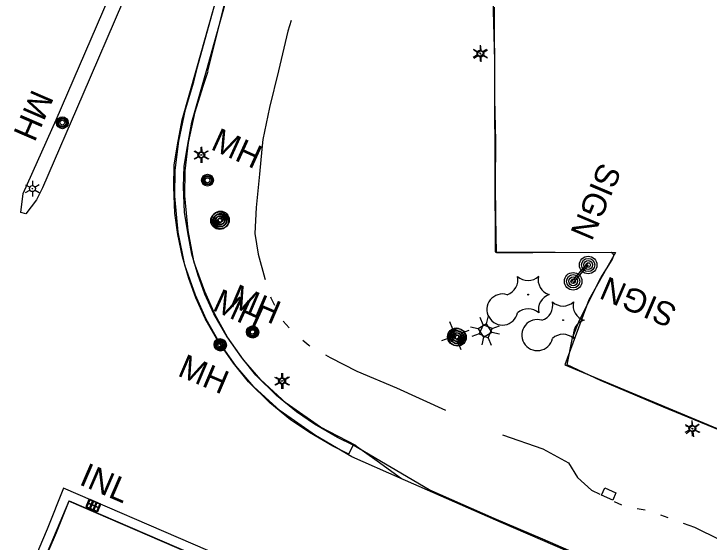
# Model space of a CAD drawing. Extents: x 588843 to 2552415, y 180129 to 269402.
# Drawn here: x 593439.7 to 593615.7, y 185762.9 to 185896.7 of the extents above; entities that cross this region are included whole.
import ezdxf

# ---------------------------------------------------------------- set-up
doc = ezdxf.new("R2010")
doc.units = 0
for name, color, linetype in [('Default', 7, 'Continuous'), ('E_AREA', 7, 'Continuous'), ('E_DRN', 7, 'Continuous'), ('E_DRN_Text', 7, 'Continuous'), ('E_DWY', 7, 'Continuous'), ('E_LAND_Vegetation', 7, 'Continuous'), ('E_LTG', 7, 'Continuous'), ('E_MISCPROP', 7, 'Continuous'), ('E_RDWY', 7, 'Continuous'), ('E_RDWY_C_and_G', 7, 'Continuous'), ('E_RDWY_Gravel', 7, 'Continuous'), ('E_SGN', 7, 'Continuous'), ('E_SGN_Text', 7, 'Continuous'), ('E_UTL_AG_Bold', 7, 'Continuous'), ('E_UTL_MH', 7, 'Continuous'), ('E_UTL_MH_Text', 7, 'Continuous'), ('E_WTR_P', 7, 'Continuous')]:
    doc.layers.add(name, color=color, linetype=linetype)

# ---------------------------------------------------------------- blocks, each defined once
blk = doc.blocks.new('LPOL')
at = {"layer": 'Default'}
for p, q in [((-4, 0), (-1.5, 0)), ((-0.75, 1.3), (-2, 3.46)), ((0.75, 1.3), (2, 3.46)), ((1.5, 0), (4, 0)), ((-2, -3.46), (-0.75, -1.3)), ((2, -3.46), (0.75, -1.3))]:
    blk.add_line(p, q, dxfattribs=at)
for radius in [1.5, 1.5, 1.5, 0.125]:
    blk.add_circle((0, 0), radius, dxfattribs=at)
blk = doc.blocks.new('POLE')
at = {"layer": 'Default'}
for radius in [4.46, 3.35, 2.23, 1.12]:
    blk.add_circle((0, 0), radius, dxfattribs=at)
blk = doc.blocks.new('MHO')
at = {"layer": 'Default'}
for centre, radius in [((0.08, -0.12), 3), ((0.08, -0.12), 2.43), ((0.07, -0.15), 1.94), ((0.02, -0.16), 1.21)]:
    blk.add_circle(centre, radius, dxfattribs=at)
blk = doc.blocks.new('MHT')
at = {"layer": 'E_UTL_MH_Text'}
blk.add_text('MH', height=12, dxfattribs=at).set_placement((-9.81, -6))
blk = doc.blocks.new('PED')
at = {"layer": 'Default'}
for p, q in [((-2.5, 2.5), (-5.33, 5.33)), ((2.5, 2.5), (5.33, 5.33)), ((-2.5, -2.5), (-5.33, -5.33)), ((2.5, -2.5), (5.33, -5.33))]:
    blk.add_line(p, q, dxfattribs=at)
blk.add_lwpolyline([(-2.5, -2.5), (2.5, -2.5), (2.5, 2.5), (-2.5, 2.5)], close=True, dxfattribs=at)
blk = doc.blocks.new('SIGN')
at = {"layer": 'Default'}
blk.add_text('SIGN', height=12, dxfattribs=at).set_placement((-18.55, -6))
blk = doc.blocks.new('CTRE')
at = {"layer": 'Default'}
blk.add_circle((0, 0), 0.223, dxfattribs=at)
for centre, start, end in [((-11.97, 8.96), 280.2067, 5.9716), ((1.81, 14.92), 220.2113, 305.9762), ((13.83, 5.89), 160.2113, 245.9762), ((-13.83, -5.9), 340.2113, 65.9762), ((12.03, -9.04), 185.9272, 100.2511), ((-1.81, -14.93), 40.2113, 125.9762)]:
    blk.add_arc(centre, 7.87, start, end, dxfattribs=at)
blk = doc.blocks.new('INLO')
at = {"layer": 'E_DRN'}
for p, q in [((2, -4), (2, 0)), ((4, -4), (4, 0)), ((6, -2), (0, -2))]:
    blk.add_line(p, q, dxfattribs=at)
blk.add_lwpolyline([(0, -4), (6, -4), (6, 0), (0, 0), (0, -4)], close=True, dxfattribs=at)
blk = doc.blocks.new('INLT_25')
at = {"layer": 'E_DRN_Text'}
blk.add_text('INL', height=12, dxfattribs=at).set_placement((-11.03, -6))
blk = doc.blocks.new('INLO_3')
at = {"layer": 'E_DRN'}
for p, q in [((6.6, -13.1), (6.6, 0)), ((13.1, -13.1), (13.1, 0)), ((19.7, -6.6), (0, -6.6))]:
    blk.add_line(p, q, dxfattribs=at)
blk.add_lwpolyline([(0, -13.1), (19.7, -13.1), (19.7, 0), (0, 0)], close=True, dxfattribs=at)
blk = doc.blocks.new('INLT_39_1')
at = {"layer": 'E_DRN_Text'}
blk.add_text('INL', height=39.37, dxfattribs=at).set_placement((-36.2, -19.7))
blk = doc.blocks.new('MHO_3')
at = {"layer": 'E_UTL_MH'}
for centre, radius in [((0.3, -0.4), 9.84), ((0.3, -0.4), 7.98), ((0.2, -0.5), 6.35), ((0.1, -0.5), 3.97)]:
    blk.add_circle(centre, radius, dxfattribs=at)
blk = doc.blocks.new('MHT_3')
at = {"layer": 'E_UTL_MH_Text'}
blk.add_text('MH', height=39.37, dxfattribs=at).set_placement((-32.2, -19.7))
blk = doc.blocks.new('PED_3')
at = {"layer": 'E_UTL_AG_Bold'}
for p, q in [((-8.2, 8.2), (-17.5, 17.5)), ((8.2, 8.2), (17.5, 17.5)), ((-8.2, -8.2), (-17.5, -17.5)), ((8.2, -8.2), (17.5, -17.5))]:
    blk.add_line(p, q, dxfattribs=at)
blk.add_lwpolyline([(-8.2, -8.2), (8.2, -8.2), (8.2, 8.2), (-8.2, 8.2)], close=True, dxfattribs=at)
blk = doc.blocks.new('LPOL_4')
at = {"layer": 'E_LTG'}
for p, q in [((-13.1, 0), (-4.9, 0)), ((-2.5, 4.3), (-6.6, 11.4)), ((2.5, 4.3), (6.6, 11.4)), ((4.9, 0), (13.1, 0)), ((-6.6, -11.4), (-2.5, -4.3)), ((6.6, -11.4), (2.5, -4.3))]:
    blk.add_line(p, q, dxfattribs=at)
for radius in [4.92, 4.92, 4.92, 0.41]:
    blk.add_circle((0, 0), radius, dxfattribs=at)
blk = doc.blocks.new('POLE_3')
at = {"layer": 'E_MISCPROP'}
for radius in [14.6, 11, 7.32, 3.66]:
    blk.add_circle((0, 0), radius, dxfattribs=at)
blk = doc.blocks.new('SIGN_3')
at = {"layer": 'E_SGN'}
blk.add_text('SIGN', height=39.37, dxfattribs=at).set_placement((-56.1, -19.7))

msp = doc.modelspace()

# ---------------------------------------------------------------- linework, layer by layer
at = {"layer": 'E_AREA'}
msp.add_lwpolyline([(593591.34, 185773.52), (593588.51, 185774.78), (593589.34, 185776.65), (593592.17, 185775.39), (593591.34, 185773.52)], close=True, dxfattribs=at)
at = {"layer": 'E_DWY'}
for points in [[(593561.3, 185898.37), (593561.59, 185836.43), (593592.09, 185836.3), (593585.32, 185824.31), (593579.2, 185807.78), (593629.08, 185786.97), (593683.34, 185763.77), (593715.78, 185763.83), (593758.03, 185763.57), (593758.13, 185803.19), (593757.72, 185847.98), (593757.71, 185903.71), (593757.53, 185954.3)], [(593626.39, 185787.96), (593604.22, 185797.06), (593588.26, 185803.86), (593579.8, 185807.78), (593581.19, 185814.63), (593582.97, 185819.1), (593588.33, 185829.86), (593591.19, 185834.44), (593591.67, 185835.51), (593591.5, 185835.94), (593590.92, 185836.23), (593571.13, 185836.15), (593561.94, 185836.17), (593561.79, 185845.33), (593561.7, 185853.71), (593561.78, 185864.51), (593561.53, 185875.2), (593561.46, 185884.92), (593561.05, 185900.77)]]:
    msp.add_lwpolyline(points, dxfattribs=at)
at = {"layer": 'E_RDWY'}
for points in [[(593486.2, 185883.3), (593489.18, 185893.96), (593493.89, 185911.07), (593499.24, 185928.93), (593507.1, 185955.12), (593509.61, 185962.65), (593517.48, 185983.79), (593527.72, 186012.54), (593531.1, 186022.16), (593535.59, 186036.96), (593539.47, 186051.68), (593541.2, 186062.67), (593545.15, 186089.33), (593548.03, 186107.77), (593551.11, 186127.76), (593554.74, 186154.6), (593556.82, 186170.65)], [(593491.32, 185955.6), (593483.2, 185936.21), (593475.03, 185917.29), (593467.27, 185899.56), (593457.19, 185876.3), (593446.96, 185852.66), (593445.45, 185849.57), (593442.79, 185846.03), (593441.53, 185846.44), (593442.11, 185851.19), (593450.4, 185869.87), (593465.24, 185904.11), (593481.63, 185942.45), (593487.18, 185955.06)], [(593486.07, 185882.94), (593490.12, 185897.35), (593494.11, 185911.31), (593497.9, 185924.36), (593502.15, 185939.12), (593506.3, 185953.15)], [(593759.1, 185683.31), (593742.04, 185690.53), (593728.3, 185696.69), (593709.33, 185704.73), (593695.77, 185710.83), (593682.84, 185716.47), (593670.2, 185721.87), (593658.17, 185727.03), (593647.4, 185731.86), (593631.92, 185738.54), (593621.67, 185743), (593610.57, 185747.71), (593598.94, 185752.59), (593585.45, 185758.54), (593573.64, 185763.64), (593561.33, 185768.89), (593544.91, 185776.17), (593525.62, 185787.49)], [(593759.23, 185683.39), (593739.55, 185691.58), (593712.69, 185703.4), (593684.94, 185715.45), (593651.85, 185729.61), (593625.47, 185740.91), (593596.7, 185753.38), (593563.11, 185767.85), (593537.55, 185779.12), (593525.28, 185784.5)]]:
    msp.add_lwpolyline(points, dxfattribs=at)
msp.add_lwpolyline([(593453.69, 185773.4), (593523.56, 185743.19), (593588.11, 185715.4), (593631.1, 185696.92), (593667.51, 185681.1), (593666.73, 185678.74), (593618.51, 185694.03), (593571.62, 185708.83), (593555.14, 185714.19), (593536.4, 185722.25), (593496.73, 185739.41), (593448.26, 185760.34), (593453.69, 185773.4)], close=True, dxfattribs=at)
at = {"layer": 'E_RDWY_C_and_G'}
msp.add_line((593524.54, 185785.23), (593525.62, 185787.49), dxfattribs=at)
for points in [[(593525.28, 185784.5), (593516.08, 185789.89), (593507.12, 185796.18), (593500.49, 185802.26), (593495.89, 185807.55), (593491.73, 185813.52), (593488.45, 185819.36), (593485.74, 185825.44), (593482.99, 185833.08), (593481.36, 185841.45), (593480.5, 185850.56), (593480.6, 185857.14), (593481.52, 185864.5), (593483.18, 185872.5), (593485.32, 185879.46), (593486.2, 185883.3)], [(593524.54, 185785.23), (593520.46, 185787.18), (593514.54, 185790.64), (593509.77, 185793.89), (593504.56, 185798.16), (593499.13, 185803.52), (593495.33, 185808.28), (593491.66, 185813.55), (593488.12, 185819.59), (593485.79, 185824.76), (593484.01, 185829.67), (593482.39, 185835.21), (593481.28, 185840.87), (593480.44, 185846.23), (593480.21, 185852.92), (593480.35, 185858.38), (593481.19, 185863.53), (593482.38, 185869.88), (593486.07, 185882.94)], [(593525.62, 185787.49), (593521.63, 185789.39), (593515.87, 185792.75), (593511.27, 185795.89), (593506.24, 185800.02), (593501, 185805.19), (593497.34, 185809.78), (593493.77, 185814.9), (593490.34, 185820.74), (593488.11, 185825.7), (593486.38, 185830.45), (593484.82, 185835.81), (593483.74, 185841.3), (593482.93, 185846.46), (593482.71, 185852.93), (593482.84, 185858.15), (593483.65, 185863.1), (593484.82, 185869.31), (593488.48, 185882.26)], [(593526.49, 185787.32), (593517.38, 185792.03), (593508.69, 185798.13), (593502.28, 185804.01), (593497.86, 185809.09), (593493.85, 185814.85), (593490.68, 185820.48), (593488.06, 185826.38), (593485.4, 185833.75), (593483.84, 185841.81), (593483, 185850.66), (593483.1, 185856.96), (593483.98, 185864.09), (593485.61, 185871.88), (593487.7, 185878.69), (593488.91, 185882.24)]]:
    msp.add_lwpolyline(points, dxfattribs=at)
for points in [[(593448.13, 185766.21), (593446.03, 185761.25), (593445.89, 185760.73), (593445.4, 185758.88), (593471.82, 185747.59), (593502.39, 185734.18), (593537.96, 185718.62), (593551.21, 185713.11), (593555.3, 185711.56), (593576.13, 185704.66), (593609.59, 185694.25), (593642.06, 185683.63), (593668.03, 185675.84), (593670.7, 185682.2), (593650.33, 185690.99), (593611.9, 185707.52), (593580.22, 185721.35), (593554.46, 185732.38), (593530.38, 185742.76), (593496.85, 185757.3), (593485.12, 185762.4), (593452.33, 185776.58)], [(593484.13, 185760.1), (593453.68, 185773.27), (593450.44, 185765.26), (593448.36, 185760.33), (593472.81, 185749.89), (593503.4, 185736.47), (593538.94, 185720.91), (593552.13, 185715.43), (593556.13, 185713.91), (593576.9, 185707.03), (593610.35, 185696.63), (593642.8, 185686.01), (593666.59, 185678.87), (593667.44, 185680.89), (593649.35, 185688.7), (593610.91, 185705.23), (593579.23, 185719.06), (593553.48, 185730.09), (593529.39, 185740.47), (593495.86, 185755.01)]]:
    msp.add_lwpolyline(points, close=True, dxfattribs=at)
at = {"layer": 'E_RDWY_Gravel'}
for points in [[(593488.82, 185882.27), (593492.95, 185898.78), (593497.36, 185916.15), (593501.01, 185930), (593507.22, 185955.48)], [(593488.48, 185882.26), (593493.13, 185898.88), (593496.57, 185912.37), (593500.46, 185927.75), (593501.95, 185933.67), (593505.72, 185948.6), (593506.3, 185953.15)], [(593526.45, 185787.23), (593531.75, 185783.51), (593537.84, 185778.99)]]:
    msp.add_lwpolyline(points, dxfattribs=at)
at = {"layer": 'E_SGN'}
msp.add_line((593585.15, 185833.11), (593581.14, 185828.46), dxfattribs=at)
msp.add_lwpolyline([(593581.02, 185828.92), (593585.01, 185833.56)], dxfattribs=at)
at = {"layer": 'E_WTR_P'}
for points in [[(593509.9, 185895.03), (593509.12, 185892.32), (593506.77, 185882.26), (593504.49, 185872.96), (593502.78, 185864.91), (593502.54, 185862.44)], [(593502.54, 185862.44), (593501.94, 185856.15), (593501.07, 185847.66), (593500.71, 185841.06), (593501.59, 185835.88), (593503.3, 185829.7), (593503.38, 185829.42)], [(593504.73, 185825.02), (593504.81, 185824.75), (593505.73, 185822.94)], [(593507.93, 185818.91), (593509.45, 185817.18)], [(593512.86, 185814.1), (593514.39, 185812.81), (593514.66, 185812.66)], [(593518.65, 185810.35), (593519.82, 185809.68), (593526.52, 185806.22), (593536.64, 185802.01), (593548.99, 185796.32)], [(593563.43, 185790.11), (593573.68, 185786.52), (593580.16, 185782.97), (593582.45, 185779.28), (593585.96, 185776.09), (593588.05, 185775.07)], [(593591.71, 185773.24), (593593.54, 185772.32)], [(593597.52, 185771.47), (593599.54, 185771.11)], [(593603.41, 185769.81), (593605.34, 185769.12)], [(593609.19, 185767.74), (593612.06, 185766.71), (593631.41, 185757.17), (593635.93, 185754.95)]]:
    msp.add_lwpolyline(points, dxfattribs=at)

# ---------------------------------------------------------------- block references
at = {"layer": 'E_DRN'}
for name, p, xscale, yscale, rotation in [('INLO', (593458.72, 185773.67), 0.4999999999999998, 0.49999999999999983, -21.589004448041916), ('INLO_3', (593459.01, 185773.7), 0.1524003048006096, 0.1524003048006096, -23.401029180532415)]:
    msp.add_blockref(name, p, dxfattribs=dict(at, xscale=xscale, yscale=yscale, rotation=rotation))
at = {"layer": 'E_DRN_Text'}
for name, p, xscale, yscale, rotation in [('INLT_25', (593462.27, 185778.18), 0.49999999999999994, 0.5000000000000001, -23.33669759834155), ('INLT_39_1', (593462.28, 185778.18), 0.1524003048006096, 0.1524003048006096, -23.401029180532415)]:
    msp.add_blockref(name, p, dxfattribs=dict(at, xscale=xscale, yscale=yscale, rotation=rotation))
at = {"layer": 'E_LAND_Vegetation', "xscale": 0.5, "yscale": 0.5, "rotation": -112.98358720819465}
for p in [(593569.94, 185825.6), (593578.77, 185819.13)]:
    msp.add_blockref('CTRE', p, dxfattribs=at)
at = {"layer": 'E_LTG'}
for name, p, xscale, yscale, rotation in [('LPOL', (593557.76, 185886.77), 0.5000000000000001, 0.5, -89.67337617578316), ('LPOL_4', (593557.93, 185886.56), 0.1524003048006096, 0.1524003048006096, -89.2544447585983), ('LPOL', (593487.06, 185860.97), 0.5000000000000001, 0.5, -89.67337617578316), ('LPOL_4', (593487.3, 185861), 0.1524003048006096, 0.1524003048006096, -89.2544447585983), ('LPOL', (593444.43, 185852.45), 0.5000000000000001, 0.5, -89.67337617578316), ('LPOL', (593507.49, 185803.73), 0.5000000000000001, 0.5, -89.67337617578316), ('LPOL_4', (593507.79, 185803.75), 0.1524003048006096, 0.1524003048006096, -89.2544447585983), ('LPOL', (593611.41, 185791.75), 0.5000000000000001, 0.5, -89.67337617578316), ('LPOL_4', (593611.6, 185791.59), 0.1524003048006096, 0.15240030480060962, -84.36014555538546)]:
    msp.add_blockref(name, p, dxfattribs=dict(at, xscale=xscale, yscale=yscale, rotation=rotation))
at = {"layer": 'E_MISCPROP'}
for name, p, xscale, yscale, rotation in [('POLE', (593491.82, 185844.33), 0.5000000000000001, 0.5, -89.67337617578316), ('POLE_3', (593492.04, 185844.52), 0.1524003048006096, 0.1524003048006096, -89.2544447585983), ('POLE_3', (593585.14, 185833.11), 0.1524003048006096, 0.1524003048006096, -89.2544447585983), ('POLE_3', (593581.33, 185828.98), 0.1524003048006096, 0.1524003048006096, -89.2544447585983), ('POLE', (593551.77, 185814.92), 0.5000000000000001, 0.5, -89.67337617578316), ('POLE_3', (593552.06, 185814.79), 0.1524003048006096, 0.1524003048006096, -89.2544447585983)]:
    msp.add_blockref(name, p, dxfattribs=dict(at, xscale=xscale, yscale=yscale, rotation=rotation))
at = {"layer": 'E_SGN_Text'}
for name, p, xscale, yscale, rotation in [('SIGN', (593587.31, 185849.65), 0.5, 0.5, -112.98358720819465), ('SIGN_3', (593598.99, 185823.2), 0.1524003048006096, 0.15240030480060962, 156.76422909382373)]:
    msp.add_blockref(name, p, dxfattribs=dict(at, xscale=xscale, yscale=yscale, rotation=rotation))
at = {"layer": 'E_UTL_AG_Bold'}
for name, p, xscale, yscale, rotation in [('PED', (593559.03, 185816.52), 0.4999999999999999, 0.4999999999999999, -57.756605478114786), ('PED_3', (593559.17, 185816.34), 0.1524003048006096, 0.1524003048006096, 156.5196793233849), ('PED_3', (593551.51, 185815.24), 0.1524003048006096, 0.1524003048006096, 156.5196793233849)]:
    msp.add_blockref(name, p, dxfattribs=dict(at, xscale=xscale, yscale=yscale, rotation=rotation))
at = {"layer": 'E_UTL_MH'}
for name, p, xscale, yscale, rotation in [('MHO', (593452.07, 185869.14), 0.4999999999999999, 0.49999999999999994, -113.37414845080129), ('MHO_3', (593488.68, 185854.57), 0.1524003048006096, 0.15240030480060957, 69.36716486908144), ('MHO', (593500.17, 185816.17), 0.4999999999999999, 0.49999999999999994, -113.37414845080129), ('MHO_3', (593500.22, 185816.18), 0.1524003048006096, 0.1524003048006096, -24.02558251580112), ('MHO', (593491.98, 185812.99), 0.4999999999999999, 0.49999999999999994, -113.37414845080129), ('MHO_3', (593492.01, 185812.88), 0.15240030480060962, 0.15240030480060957, -24.440434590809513)]:
    msp.add_blockref(name, p, dxfattribs=dict(at, xscale=xscale, yscale=yscale, rotation=rotation))
at = {"layer": 'E_UTL_MH_Text'}
for name, p, xscale, yscale, rotation in [('MHT', (593445.24, 185872.17), 0.4999999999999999, 0.49999999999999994, -113.37414845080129), ('MHT_3', (593495.01, 185863.22), 0.15240030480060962, 0.15240030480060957, -24.440434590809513), ('MHT_3', (593495.44, 185822.47), 0.15240030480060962, 0.15240030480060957, -24.440434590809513), ('MHT', (593499.74, 185823.7), 0.5000000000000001, 0.4999999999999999, -23.108396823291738), ('MHT', (593486.61, 185806), 0.5000000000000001, 0.4999999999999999, -23.108396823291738)]:
    msp.add_blockref(name, p, dxfattribs=dict(at, xscale=xscale, yscale=yscale, rotation=rotation))

doc.saveas('drawing.dxf')
